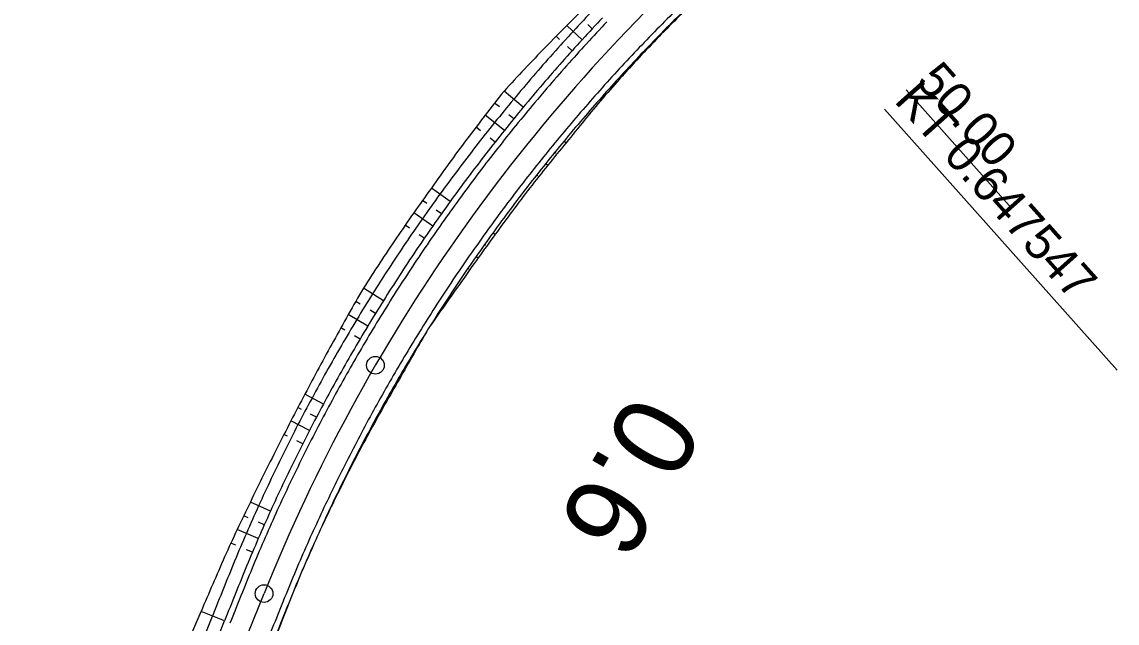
# Model space of a CAD drawing. Extents: x -481645 to -478728, y -1113199 to -1110710.
# Drawn here: x -480212.6 to -480119.6, y -1112558.2 to -1112507.2 of the extents above; entities that cross this region are included whole.
import ezdxf

# ---------------------------------------------------------------- set-up
doc = ezdxf.new("R2010")
doc.units = 0
for name, color, linetype in [('Vrstva 52', 7, 'Continuous'), ('Vrstva 53', 7, 'Continuous'), ('Vrstva 54', 7, 'Continuous'), ('Vrstva 55', 7, 'Continuous'), ('Vrstva 56', 7, 'Continuous'), ('Vrstva 57', 7, 'Continuous'), ('Vrstva 58', 7, 'Continuous'), ('Vrstva 59', 7, 'Continuous'), ('Vrstva 60', 7, 'Continuous'), ('Vrstva 61', 7, 'Continuous'), ('Vrstva 62', 7, 'Continuous')]:
    doc.layers.add(name, color=color, linetype=linetype)

msp = doc.modelspace()

# ---------------------------------------------------------------- linework, layer by layer
at = {"layer": 'Vrstva 52'}
msp.add_line((-480212.635, -1112606.944), (-480192.068, -1112555.732), dxfattribs=at)
msp.add_arc((-480052.874, -1112611.634), 150, 131.70774, 158.11863, dxfattribs=at)
at = {"layer": 'Vrstva 53'}
msp.add_line((-480199.402, -1112561.842), (-480197.419, -1112557.25), dxfattribs=at)
for centre, radius, start, end in [((-480057.212, -1112616.172), 154.031, 134.16481, 136.07626), ((-480052.61, -1112611.365), 147.686, 134.73676, 136.64662), ((-480057.652, -1112616.948), 154.255, 135.75538, 137.66729), ((-480051.656, -1112610.291), 147.65, 137.20406, 139.11406), ((-480051.27, -1112609.599), 154.331, 141.28188, 143.19201), ((-480050.819, -1112609.186), 147.566, 139.65113, 141.56144), ((-480051.537, -1112609.82), 154.25, 143.06701, 144.97708), ((-480053.154, -1112611.983), 147.52, 140.14636, 142.05622), ((-480053.006, -1112611.824), 154.216, 144.05414, 145.964), ((-480052.619, -1112611.292), 147.521, 142.39574, 144.30561), ((-480053.449, -1112612.513), 154.238, 145.65961, 147.56951), ((-480053.795, -1112612.94), 147.54, 143.51934, 145.42931), ((-480055.924, -1112616.148), 147.658, 143.93555, 145.84671), ((-480050.572, -1112607.686), 154.179, 149.65754, 151.56824), ((-480051.193, -1112608.774), 147.693, 149.24633, 151.15667), ((-480051.763, -1112609.609), 154.064, 150.72827, 152.63834), ((-480053.372, -1112612.519), 147.655, 149.47557, 151.38548), ((-480052.967, -1112611.814), 154.029, 151.7042, 153.61406), ((-480053.341, -1112612.533), 147.689, 151.38654, 153.29644), ((-480054.062, -1112614.085), 154.078, 152.67639, 154.58655), ((-480053.311, -1112612.549), 147.722, 153.29613, 155.20603), ((-480054.738, -1112615.766), 154.199, 153.91455, 155.82524), ((-480052.901, -1112611.696), 147.74, 155.57286, 157.48271), ((-479771.693, -1112738.806), 462.824, 156.27879, 156.90362), ((-479778.643, -1112721.686), 443.225, 157.92555, 158.5688)]:
    msp.add_arc(centre, radius, start, end, dxfattribs=at)
at = {"layer": 'Vrstva 54'}
msp.add_line((-480198.32, -1112562.277), (-480196.453, -1112557.638), dxfattribs=at)
for centre, radius, start, end in [((-480053.067, -1112611.844), 153.292, 136.39406, 138.30392), ((-480053.06, -1112611.85), 153.302, 138.30393, 140.21379), ((-480053.053, -1112611.857), 153.311, 140.21362, 142.12348), ((-480053.044, -1112611.862), 153.321, 142.12383, 144.03369), ((-480053.022, -1112611.846), 153.33, 144.04361, 145.95347), ((-480052.945, -1112611.744), 153.336, 146.00085, 147.91071), ((-480052.928, -1112611.723), 153.34, 147.9208, 149.83066), ((-480052.925, -1112611.726), 153.344, 149.83049, 151.74035), ((-480052.922, -1112611.727), 153.347, 151.74052, 153.65038), ((-480052.918, -1112611.728), 153.35, 153.65038, 155.56024), ((-480052.915, -1112611.73), 153.354, 155.56024, 157.4701), ((-479769.008, -1112727.793), 460.067, 157.66668, 158.29382)]:
    msp.add_arc(centre, radius, start, end, dxfattribs=at)
at = {"layer": 'Vrstva 55'}
msp.add_line((-480197.287, -1112562.691), (-480195.424, -1112558.052), dxfattribs=at)
for centre, radius, start, end in [((-480052.874, -1112611.634), 152.25, 136.50047, 138.41033), ((-480052.874, -1112611.634), 147.75, 134.59061, 136.50047), ((-480052.874, -1112611.634), 152.25, 138.41033, 140.32019), ((-480052.874, -1112611.634), 147.75, 136.50047, 138.41033), ((-480052.874, -1112611.634), 147.75, 138.41033, 140.32019), ((-480052.874, -1112611.634), 152.25, 140.32019, 142.23005), ((-480052.874, -1112611.634), 147.75, 140.32019, 142.23005), ((-480052.874, -1112611.634), 152.25, 142.23005, 144.13991), ((-480052.874, -1112611.634), 147.75, 142.23005, 144.13991), ((-480052.874, -1112611.634), 152.25, 144.13991, 146.04977), ((-480052.874, -1112611.634), 147.75, 144.13991, 146.04976), ((-480052.874, -1112611.634), 152.25, 146.04977, 147.95963), ((-480052.874, -1112611.634), 147.75, 146.04977, 147.95963), ((-480052.874, -1112611.634), 152.25, 147.95963, 149.86949), ((-480052.874, -1112611.634), 147.75, 147.95962, 149.86948), ((-480052.874, -1112611.634), 152.25, 149.86949, 151.77934), ((-480052.874, -1112611.634), 147.75, 149.86948, 151.77934), ((-480052.874, -1112611.634), 152.25, 151.77934, 153.6892), ((-480052.874, -1112611.634), 147.75, 151.77934, 153.6892), ((-480052.874, -1112611.634), 152.25, 153.6892, 155.59906), ((-480052.874, -1112611.634), 147.75, 153.6892, 155.59906), ((-480052.874, -1112611.634), 152.25, 155.59906, 157.50892), ((-480052.874, -1112611.634), 147.75, 155.59906, 157.50892), ((-479770.938, -1112726.671), 456.75, 157.70521, 158.33543), ((-479779.285, -1112723.303), 443.25, 157.70069, 158.34391)]:
    msp.add_arc(centre, radius, start, end, dxfattribs=at)
at = {"layer": 'Vrstva 56'}
for centre, radius, start, end in [((-480052.874, -1112611.634), 148.25, 134.59061, 136.50047), ((-480052.874, -1112611.634), 151.75, 136.50047, 138.41033), ((-480052.874, -1112611.634), 148.25, 136.50047, 138.41033), ((-480052.874, -1112611.634), 151.75, 138.41033, 140.32019), ((-480052.874, -1112611.634), 148.25, 138.41033, 140.32019), ((-480052.874, -1112611.634), 151.75, 140.32019, 142.23005), ((-480052.874, -1112611.634), 148.25, 140.32019, 142.23005), ((-480052.874, -1112611.634), 151.75, 142.23005, 144.13991), ((-480052.874, -1112611.634), 148.25, 142.23005, 144.13991), ((-480052.874, -1112611.634), 151.75, 144.13991, 146.04977), ((-480052.874, -1112611.634), 148.25, 144.13991, 146.04976), ((-480052.874, -1112611.634), 151.75, 146.04977, 147.95963), ((-480052.874, -1112611.634), 148.25, 146.04977, 147.95963), ((-480052.874, -1112611.634), 151.75, 147.95962, 149.86948), ((-480052.874, -1112611.634), 148.25, 147.95962, 149.86948), ((-480052.874, -1112611.634), 151.75, 149.86949, 151.77934), ((-480052.874, -1112611.634), 148.25, 149.86948, 151.77934), ((-480052.874, -1112611.634), 151.75, 151.77934, 153.6892), ((-480052.874, -1112611.634), 148.25, 151.77934, 153.6892), ((-480052.874, -1112611.634), 151.75, 153.6892, 155.59906), ((-480052.874, -1112611.634), 148.25, 153.6892, 155.59906), ((-480052.874, -1112611.634), 151.75, 155.59906, 157.50892), ((-480052.874, -1112611.634), 148.25, 155.59906, 157.50892), ((-479771.866, -1112726.297), 455.25, 157.70473, 158.33635), ((-479778.357, -1112723.677), 444.75, 157.70121, 158.34295)]:
    msp.add_arc(centre, radius, start, end, dxfattribs=at)
at = {"layer": 'Vrstva 57'}
for centre, radius, start, end in [((-480052.874, -1112611.634), 148.25, 134.59061, 136.50047), ((-480052.874, -1112611.634), 151.75, 136.50047, 138.41033), ((-480052.874, -1112611.634), 148.25, 136.50047, 138.41033), ((-480052.874, -1112611.634), 151.75, 138.41033, 140.32019), ((-480052.874, -1112611.634), 148.25, 138.41033, 140.32019), ((-480052.874, -1112611.634), 151.75, 140.32019, 142.23005), ((-480052.874, -1112611.634), 148.25, 140.32019, 142.23005), ((-480052.874, -1112611.634), 151.75, 142.23005, 144.13991), ((-480052.874, -1112611.634), 148.25, 142.23005, 144.13991), ((-480052.874, -1112611.634), 151.75, 144.13991, 146.04977), ((-480052.874, -1112611.634), 148.25, 144.13991, 146.04976), ((-480052.874, -1112611.634), 151.75, 146.04977, 147.95963), ((-480052.874, -1112611.634), 148.25, 146.04977, 147.95963), ((-480052.874, -1112611.634), 151.75, 147.95962, 149.86948), ((-480052.874, -1112611.634), 148.25, 147.95962, 149.86948), ((-480052.874, -1112611.634), 151.75, 149.86949, 151.77934), ((-480052.874, -1112611.634), 148.25, 149.86948, 151.77934), ((-480052.874, -1112611.634), 151.75, 151.77934, 153.6892), ((-480052.874, -1112611.634), 148.25, 151.77934, 153.6892), ((-480052.874, -1112611.634), 151.75, 153.6892, 155.59906), ((-480052.874, -1112611.634), 148.25, 153.6892, 155.59906), ((-480052.874, -1112611.634), 151.75, 155.59906, 157.50892), ((-480052.874, -1112611.634), 148.25, 155.59906, 157.50892), ((-479771.866, -1112726.297), 455.25, 157.70473, 158.33635), ((-479778.357, -1112723.677), 444.75, 157.70121, 158.34295)]:
    msp.add_arc(centre, radius, start, end, dxfattribs=at)
at = {"layer": 'Vrstva 58'}
msp.add_line((-480137.536, -1112512.951), (-480128.554, -1112523.03), dxfattribs=at)
at = {"layer": 'Vrstva 59'}
msp.add_line((-480139.367, -1112514.583), (-480119.607, -1112536.756), dxfattribs=at)
msp.add_circle((-480192.068, -1112555.732), 0.75, dxfattribs=at)
at = {"layer": 'Vrstva 60'}
msp.add_circle((-480182.607, -1112536.339), 0.75, dxfattribs=at)
at = {"layer": 'Vrstva 61'}
for p, q in [((-480165.044, -1112508.688), (-480166.356, -1112507.484)), ((-480164.182, -1112507.757), (-480164.562, -1112507.402)), ((-480166.966, -1112508.662), (-480167.259, -1112508.398)), ((-480165.898, -1112509.627), (-480166.286, -1112509.277)), ((-480170.049, -1112514.423), (-480171.684, -1112513.067)), ((-480172.08, -1112514.404), (-480172.485, -1112514.074)), ((-480171.653, -1112516.39), (-480173.277, -1112515.088)), ((-480170.855, -1112515.403), (-480171.266, -1112515.068)), ((-480173.669, -1112516.416), (-480174.06, -1112516.108)), ((-480172.443, -1112517.383), (-480172.86, -1112517.054)), ((-480176.265, -1112522.445), (-480177.855, -1112521.295)), ((-480178.244, -1112522.596), (-480178.606, -1112522.339)), ((-480177.734, -1112524.514), (-480179.347, -1112523.389)), ((-480177.004, -1112523.477), (-480177.443, -1112523.165)), ((-480179.714, -1112524.696), (-480180.079, -1112524.445)), ((-480178.456, -1112525.557), (-480178.902, -1112525.252)), ((-480181.932, -1112530.863), (-480183.632, -1112529.799)), ((-480183.903, -1112531.142), (-480184.277, -1112530.912)), ((-480183.261, -1112533.025), (-480184.913, -1112532.029)), ((-480182.601, -1112531.942), (-480183.065, -1112531.656)), ((-480185.194, -1112533.356), (-480185.539, -1112533.152)), ((-480183.911, -1112534.115), (-480184.38, -1112533.837)), ((-480187.026, -1112539.64), (-480188.591, -1112538.8)), ((-480188.894, -1112540.092), (-480189.195, -1112539.933)), ((-480188.208, -1112541.886), (-480189.789, -1112541.071)), ((-480187.622, -1112540.761), (-480188.107, -1112540.506)), ((-480190.069, -1112542.367), (-480190.374, -1112542.213)), ((-480188.784, -1112543.016), (-480189.274, -1112542.768)), ((-480191.524, -1112548.737), (-480193.231, -1112547.963)), ((-480193.422, -1112549.284), (-480193.791, -1112549.12)), ((-480192.044, -1112549.895), (-480192.548, -1112549.671)), ((-480192.553, -1112551.056), (-480194.342, -1112550.281)), ((-480194.477, -1112551.619), (-480194.883, -1112551.447)), ((-480193.053, -1112552.223), (-480193.562, -1112552.007)), ((-480195.424, -1112558.052), (-480197.419, -1112557.25))]:
    msp.add_line(p, q, dxfattribs=at)
at = {"layer": 'Vrstva 62'}
for p, q in [((-480160.049, -1112509.931), (-480159.998, -1112509.979)), ((-480160.893, -1112510.828), (-480160.862, -1112510.857)), ((-480160.83, -1112510.886), (-480160.83, -1112510.886)), ((-480161.729, -1112511.731), (-480161.655, -1112511.799)), ((-480162.558, -1112512.642), (-480162.515, -1112512.68)), ((-480162.472, -1112512.719), (-480162.472, -1112512.719)), ((-480166.586, -1112517.297), (-480166.403, -1112517.448)), ((-480167.368, -1112518.247), (-480167.278, -1112518.321)), ((-480167.187, -1112518.395), (-480167.187, -1112518.395)), ((-480168.142, -1112519.205), (-480167.963, -1112519.348)), ((-480168.909, -1112520.169), (-480168.82, -1112520.238)), ((-480168.731, -1112520.308), (-480168.731, -1112520.308)), ((-480172.618, -1112525.081), (-480172.426, -1112525.22)), ((-480173.335, -1112526.082), (-480173.244, -1112526.146)), ((-480173.153, -1112526.211), (-480173.153, -1112526.211)), ((-480174.044, -1112527.089), (-480173.872, -1112527.209)), ((-480174.744, -1112528.102), (-480174.663, -1112528.158)), ((-480174.582, -1112528.213), (-480174.582, -1112528.213)), ((-480178.118, -1112533.251), (-480178.117, -1112533.251)), ((-480178.767, -1112534.297), (-480178.754, -1112534.304)), ((-480178.742, -1112534.312), (-480178.742, -1112534.312)), ((-480179.407, -1112535.349), (-480179.358, -1112535.378)), ((-480180.038, -1112536.406), (-480180.002, -1112536.428)), ((-480179.965, -1112536.449), (-480179.965, -1112536.449)), ((-480183.061, -1112541.768), (-480182.992, -1112541.805)), ((-480183.639, -1112542.855), (-480183.608, -1112542.872)), ((-480183.577, -1112542.888), (-480183.577, -1112542.888)), ((-480184.208, -1112543.948), (-480184.153, -1112543.976)), ((-480184.767, -1112545.044), (-480184.743, -1112545.056)), ((-480184.72, -1112545.068), (-480184.72, -1112545.068)), ((-480187.426, -1112550.596), (-480187.417, -1112550.6)), ((-480187.93, -1112551.719), (-480187.926, -1112551.722)), ((-480187.921, -1112551.724), (-480187.921, -1112551.724)), ((-480188.425, -1112552.847), (-480188.416, -1112552.851)), ((-480188.91, -1112553.979), (-480188.906, -1112553.98)), ((-480188.902, -1112553.982), (-480188.902, -1112553.982))]:
    msp.add_line(p, q, dxfattribs=at)

# ---------------------------------------------------------------- texts
at = {"layer": 'Vrstva 58'}
msp.add_text('50.00', height=2.999, rotation=311.70774, dxfattribs=at).set_placement((-480136.79, -1112512.285))
at = {"layer": 'Vrstva 59'}
msp.add_text('KT 0.647547', height=2.999, rotation=311.70774, dxfattribs=at).set_placement((-480138.621, -1112513.917))
at = {"layer": 'Vrstva 60'}
msp.add_text('0.6', height=7, rotation=239.82386, dxfattribs=at).set_placement((-480160.681, -1112538.42))

doc.saveas('drawing.dxf')
